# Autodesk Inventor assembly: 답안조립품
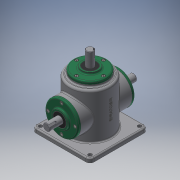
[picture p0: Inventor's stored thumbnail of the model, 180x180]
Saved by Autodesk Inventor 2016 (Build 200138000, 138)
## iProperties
Created: 2019-08
Part Number: 답안조립품
Material: 일반
Document SubType Name: Assembly
Designer: user
Author: user
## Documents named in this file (16)
- D:\490823V1010\답안조립품.iam
- D:\490823V1010\메인 베벨기어.ipt
- D:\490823V1010\메인 축.ipt
- 메인 축.ipt
- D:\490823V1010\베어링 6203.ipt
- D:\490823V1010\본체.ipt
- D:\490823V1010\볼트 M4.ipt
- 볼트 M4.ipt
- D:\490823V1010\서브 베벨기어.ipt
- D:\490823V1010\서브 축.ipt
- 서브 축.ipt
- D:\490823V1010\오일 실.ipt
- 오일 실.ipt
- D:\490823V1010\커버.ipt
- D:\490823V1010\키 4x4.ipt
- D:\490823V1010\키 5x5.ipt
